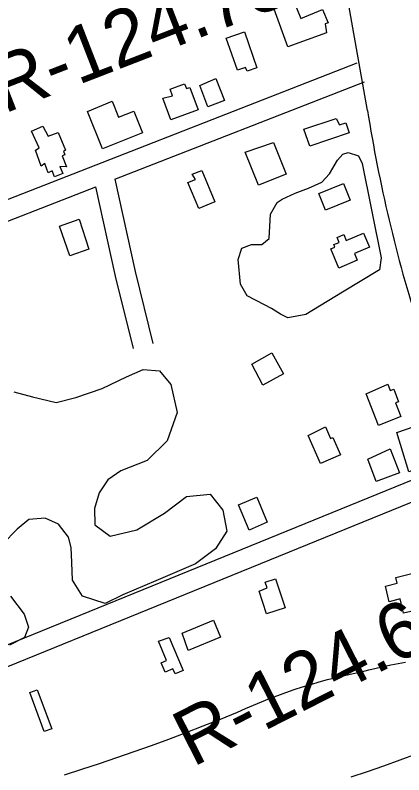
# Model space of a CAD drawing. Extents: x 3568792 to 3606828, y 529143 to 554785.
# Drawn here: x 3573679 to 3574252, y 536764 to 537886 of the extents above; entities that cross this region are included whole.
import ezdxf

# ---------------------------------------------------------------- set-up
doc = ezdxf.new("R2010")
doc.units = 0
for name, color, linetype in [('V-BLDG-OTLN', 7, 'Continuous'), ('V-RIVR-RANG-IDEN', 7, 'Continuous'), ('V-ROAD-CNTR', 7, 'Continuous'), ('V-SITE-VEGE', 7, 'Continuous')]:
    doc.layers.add(name, color=color, linetype=linetype)

msp = doc.modelspace()

# ---------------------------------------------------------------- linework, layer by layer
at = {"layer": 'V-BLDG-OTLN'}
for points in [[(3574089.1, 537907.5), (3574099.9, 537881.3), (3574132.1, 537894.5), (3574140.2, 537874.9), (3574135.8, 537873.1), (3574138.1, 537859.8), (3574080.6, 537839.1), (3574060.8, 537895)], [(3573989.8, 537852.3), (3574016.7, 537861.5), (3574035.2, 537808.3), (3574020.6, 537803.2), (3574018.6, 537809), (3574006.5, 537804.8)], [(3573974.6, 537792.7), (3573987.2, 537760), (3573963, 537750.7), (3573950.8, 537782.4)], [(3573896.6, 537763.4), (3573910.7, 537766.9), (3573907.1, 537776.8), (3573928.6, 537784.7), (3573931.2, 537777.6), (3573936.1, 537779.4), (3573948.3, 537746.5), (3573908.3, 537731.7)], [(3573821.7, 537759), (3573831.1, 537735.4), (3573853.6, 537744.4), (3573866.4, 537712.3), (3573807.2, 537688.7), (3573785.3, 537743.7)], [(3574113.1, 537692.5), (3574104.3, 537717.9), (3574152.2, 537733.3), (3574157.1, 537723.9), (3574166.5, 537727.1), (3574171.5, 537712.3)], [(3573719.2, 537722.2), (3573727.2, 537707.3), (3573741.8, 537712.6), (3573752.9, 537686.7), (3573749.7, 537685.4), (3573751.9, 537679.7), (3573748, 537678.2), (3573754.3, 537662.1), (3573744.2, 537662.5), (3573749.1, 537652.4), (3573736.5, 537647.1), (3573732.9, 537656.2), (3573727.3, 537653.1), (3573722.3, 537667.1), (3573717.1, 537663.1), (3573708.4, 537686.7), (3573713.8, 537690.1), (3573702.6, 537714.6)], [(3574059.9, 537697.9), (3574078.6, 537651.5), (3574037.7, 537635), (3574018.1, 537683.6)], [(3573953.9, 537656.8), (3573973.1, 537610.2), (3573949.4, 537600.4), (3573933.5, 537639.1), (3573944.5, 537643.6), (3573939.9, 537651.1)], [(3574172.8, 537612.9), (3574136.3, 537598.1), (3574126.4, 537622.6), (3574163, 537637.3)], [(3573787.3, 537540.7), (3573759.4, 537530.9), (3573743.9, 537574.7), (3573772.8, 537584.9)], [(3574156.5, 537550.6), (3574153.4, 537558), (3574163.4, 537562.2), (3574167.1, 537553.3), (3574192.4, 537564), (3574201.1, 537543.5), (3574179.1, 537534.2), (3574183.3, 537524.2), (3574156.2, 537512.7), (3574144.3, 537540.9), (3574150, 537543.3), (3574148.5, 537547.6)], [(3574027.5, 537370.8), (3574057.1, 537387.3), (3574074.2, 537356.7), (3574044, 537339.8)], [(3574196.4, 537326.8), (3574228.2, 537341.3), (3574231.9, 537331.8), (3574237.1, 537333.8), (3574244.3, 537315.3), (3574239.7, 537313.5), (3574247.6, 537293.3), (3574214.6, 537280.4)], [(3574276.8, 537211.7), (3574274.8, 537217.9), (3574259.3, 537211.6), (3574241.6, 537269.8), (3574292.9, 537287.7), (3574313.9, 537225.7)], [(3574111, 537265.4), (3574136.2, 537278.2), (3574143.7, 537261.1), (3574147.1, 537262.6), (3574158.3, 537236.7), (3574129, 537224)], [(3574198.7, 537230.3), (3574231.8, 537246), (3574245.5, 537210.4), (3574211.3, 537197.3)], [(3574023.9, 537125.5), (3574008, 537163.1), (3574034.9, 537174.4), (3574050.5, 537137.5)], [(3574277, 537060.3), (3574288.3, 537011.4), (3574251.7, 537002.9), (3574246.7, 537024.1), (3574230.3, 537020.1), (3574224.8, 537043.1), (3574242.2, 537047.4), (3574240.1, 537055.9), (3574266, 537062.2), (3574266.7, 537059.2)], [(3574038.3, 537035.8), (3574050.1, 537040.6), (3574047.4, 537048.8), (3574062.8, 537053.9), (3574076.9, 537011.1), (3574049.5, 537002)], [(3573925.1, 536973.7), (3573971.1, 536992.7), (3573981.5, 536967.6), (3573933.8, 536947.8)], [(3573905.8, 536967.3), (3573926.3, 536918.4), (3573914.5, 536913.4), (3573911.3, 536921), (3573899.7, 536916.2), (3573894, 536929.9), (3573901.9, 536933.2), (3573889.9, 536962)], [(3573711.2, 536889.9), (3573732.4, 536832.5), (3573721.3, 536828.4), (3573700.1, 536885.8)]]:
    msp.add_lwpolyline(points, close=True, dxfattribs=at)
at = {"layer": 'V-ROAD-CNTR'}
for points in [[(3574198.3, 537745.5), (3574123.5, 538167.3), (3574062.6, 538475), (3573995.6, 538835.1), (3573932.2, 539180.8)], [(3573603.8, 537589.2), (3574182.9, 537815.7)], [(3573825.5, 537643.7), (3574193.8, 537787.8)], [(3573825.4, 537643.7), (3573855.5, 537507.6), (3573881.6, 537401.3)], [(3572993.9, 537306.3), (3573597.9, 537554.6), (3573797.4, 537632.7)], [(3573797.2, 537632.6), (3573826.3, 537500.8), (3573852.4, 537394.1)], [(3574339.3, 537227.7), (3574291.9, 537210.9), (3573213.3, 536771.4)], [(3574349.4, 537199.4), (3574302.6, 537182.8), (3573224.7, 536743.6)]]:
    msp.add_lwpolyline(points, dxfattribs=at)
msp.add_arc((3576387.6, 538093.2), 2216.7, 189.0248, 197.557, dxfattribs=at)
at = {"layer": 'V-SITE-VEGE'}
msp.add_lwpolyline([(3574053.5, 537556.1), (3574055.4, 537592.4), (3574064.9, 537609.6), (3574072.7, 537614.5), (3574091.9, 537623.4), (3574111.1, 537630.6), (3574131.1, 537639.5), (3574142.4, 537651.9), (3574154, 537672.1), (3574161.8, 537680.9), (3574169.7, 537683.2), (3574185.1, 537678.5), (3574190.4, 537667.2), (3574218.3, 537527.8), (3574215.9, 537509.8), (3574161.4, 537477), (3574107.5, 537444.1), (3574080.8, 537439.1), (3574069.8, 537444.7), (3574056.6, 537452.9), (3574046.5, 537458.5), (3574021, 537471.4), (3574010.8, 537488.8), (3574007.8, 537525.5), (3574013, 537541.8), (3574027.3, 537547.6), (3574042.7, 537547.3)], close=True, dxfattribs=at)
for points in [[(3573676.7, 537329.7), (3573704.1, 537322.4), (3573739, 537314.4), (3573767.8, 537321.5), (3573806.8, 537334.6), (3573842.7, 537352.2), (3573867.3, 537363.1), (3573891.6, 537360.9), (3573908.2, 537340.6), (3573917.6, 537299.2), (3573902.6, 537257.5), (3573873.4, 537228.6), (3573834.4, 537213.5), (3573815.4, 537200.1), (3573802.6, 537180.9), (3573795.4, 537157.8), (3573796.2, 537133.4), (3573818.5, 537116.8), (3573858, 537126.3), (3573899.1, 537150.6), (3573931.3, 537175.2), (3573966.4, 537179), (3573984.8, 537155), (3573990.6, 537124.2), (3573973.9, 537098.2), (3573944.8, 537076.2), (3573886.3, 537050.8), (3573837.2, 537030.3), (3573811.4, 537017.5), (3573777.8, 537028.1), (3573763.1, 537052), (3573762.3, 537077.7), (3573761.3, 537100.2), (3573757.2, 537115.3), (3573742.5, 537134.3), (3573722.6, 537143.3), (3573698.8, 537141.2), (3573681.7, 537127.1), (3573660.1, 537105.5)], [(3573671.5, 537028.4), (3573691.7, 537001.8), (3573698.3, 536982.4), (3573692.4, 536967.4), (3573670.4, 536955.9)], [(3573751.1, 536764.4), (3573777, 536772.7), (3573802.8, 536781.1), (3573828.5, 536789.8), (3573854.2, 536798.7), (3573879.8, 536807.9), (3573905.3, 536817.2), (3573930.7, 536826.8), (3573956.1, 536836.6), (3573981.3, 536846.6), (3574006.5, 536856.8), (3574018.2, 536862.2), (3574030, 536867.3), (3574041.9, 536872.3), (3574053.8, 536877.1), (3574065.9, 536881.7), (3574078, 536886.1), (3574090.1, 536890.3), (3574102.4, 536894.3), (3574114.7, 536898), (3574127.1, 536901.6), (3574139.5, 536905), (3574152, 536908.2), (3574164.5, 536911.2), (3574177.1, 536913.9), (3574189.7, 536916.5), (3574200.4, 536919.4), (3574211.1, 536922.1), (3574221.9, 536924.6), (3574232.8, 536926.9), (3574243.7, 536929), (3574254.6, 536930.8)], [(3574357.8, 536863.6), (3574357.6, 536856), (3574357.3, 536848.4), (3574357, 536845.8), (3574356.5, 536843.2), (3574355.8, 536840.6), (3574355, 536838.1), (3574353.9, 536835.7), (3574352.6, 536833.4), (3574351.1, 536831.2), (3574349.5, 536829.1), (3574347.7, 536827.2), (3574345.8, 536825.4), (3574343.7, 536823.7), (3574341.5, 536822.2), (3574317.8, 536812.9), (3574294, 536803.7), (3574270.2, 536794.8), (3574246.2, 536786), (3574222.2, 536777.4), (3574198.1, 536769.1), (3574174, 536760.9)]]:
    msp.add_lwpolyline(points, dxfattribs=at)

# ---------------------------------------------------------------- texts
at = {"layer": 'V-RIVR-RANG-IDEN'}
for s, rotation, p in [('R-124.75', 21.2097, (3573661.9, 537740.2)), ('R-124.6', 26.9595, (3573940.4, 536775.1))]:
    msp.add_text(s, height=83, rotation=rotation, dxfattribs=at).set_placement(p)

doc.saveas('drawing.dxf')
